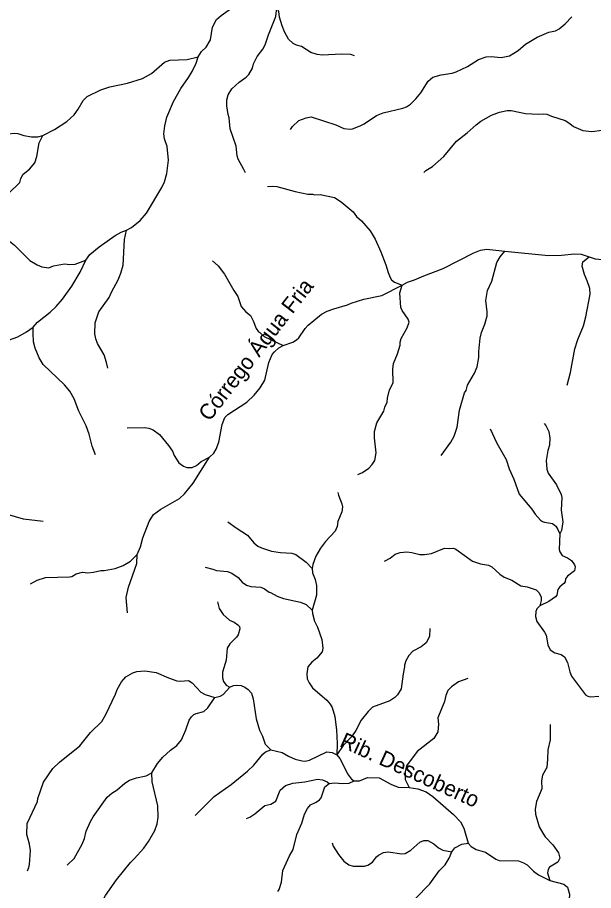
# Model space of a CAD drawing. Extents: x 500 to 555.2, y 9115.7 to 9171.
# Drawn here: x 535.02 to 540.92, y 9143.36 to 9152.3 of the extents above; entities that cross this region are included whole.
import ezdxf
from ezdxf.enums import TextEntityAlignment as Align

# ---------------------------------------------------------------- set-up
doc = ezdxf.new("R2010")
doc.units = 0
doc.header["$LTSCALE"] = 0.064
doc.layers.add('61', color=7, linetype='Continuous')
doc.layers.add('7', color=7, linetype='Continuous', lineweight=25)

msp = doc.modelspace()

# ---------------------------------------------------------------- linework, layer by layer
at = {"layer": '7'}
for points in [[(536.8687, 9151.8985), (536.9035, 9151.9524), (536.9505, 9151.9948), (536.9947, 9152.071), (537.0167, 9152.2028), (537.0572, 9152.2802), (537.1041, 9152.3224), (537.2347, 9152.4119), (537.3382, 9152.5218), (537.4017, 9152.6037), (537.575, 9152.7884), (537.6776, 9152.8682), (537.7376, 9152.9031)], [(537.3545, 9150.7074), (537.3378, 9150.7418), (537.2785, 9150.8504), (537.2688, 9150.8828), (537.2588, 9150.9811), (537.1982, 9151.1583), (537.1883, 9151.2725), (537.1754, 9151.3082), (537.1621, 9151.395), (537.1638, 9151.4579), (537.1762, 9151.5081), (537.2149, 9151.57), (537.289, 9151.638), (537.3621, 9151.6897), (537.3881, 9151.7155), (537.4259, 9151.7827), (537.4377, 9151.8242), (537.4735, 9151.8991), (537.5329, 9151.9761), (537.5572, 9152.0205), (537.5886, 9152.1227), (537.6652, 9152.3116), (537.6764, 9152.398)], [(538.473, 9151.9077), (538.4349, 9151.9208), (538.3371, 9151.9258), (538.1408, 9151.9146), (538.0893, 9151.9213), (538.0255, 9151.9405), (537.9294, 9152.0047), (537.8767, 9152.0181), (537.8419, 9152.0349), (537.7945, 9152.0795), (537.7544, 9152.152), (537.7307, 9152.2134), (537.7033, 9152.3021), (537.696, 9152.3616), (537.6764, 9152.398)], [(537.8149, 9151.1529), (537.8371, 9151.1837), (537.9019, 9151.2434), (537.9752, 9151.2728), (538.0263, 9151.283), (538.2814, 9151.2023), (538.3618, 9151.1643), (538.4278, 9151.1567), (538.45, 9151.1597), (538.5289, 9151.1889), (538.57, 9151.2111), (538.6976, 9151.2977), (538.7664, 9151.3239), (538.9664, 9151.3699), (539.0046, 9151.3841), (539.0475, 9151.4118), (539.1021, 9151.4662), (539.1515, 9151.5276), (539.2285, 9151.6465), (539.2765, 9151.688), (539.3608, 9151.7144), (539.4736, 9151.7305), (539.5155, 9151.7426), (539.6312, 9151.799), (539.7423, 9151.8685), (539.8236, 9151.8957), (539.8718, 9151.8996), (539.9748, 9151.8915), (540.0608, 9151.9088), (540.149, 9151.962), (540.2246, 9152.0259), (540.3464, 9152.0991), (540.4656, 9152.1489), (540.5345, 9152.1654), (540.5707, 9152.1856), (540.6313, 9152.2343), (540.702, 9152.3083)], [(535.2749, 9151.0905), (535.3951, 9151.1524), (535.5223, 9151.2358), (535.5956, 9151.3026), (535.6382, 9151.3617), (535.6892, 9151.4502), (535.7297, 9151.4923), (535.8696, 9151.5584), (535.9633, 9151.5908), (536.1433, 9151.6277), (536.2967, 9151.6768), (536.3887, 9151.7273), (536.5229, 9151.8412), (536.5796, 9151.8636), (536.7559, 9151.8698), (536.8687, 9151.8985)], [(536.1348, 9150.1218), (536.1835, 9150.1502), (536.2752, 9150.2221), (536.339, 9150.296), (536.4977, 9150.558), (536.5228, 9150.6183), (536.5475, 9150.7013), (536.565, 9150.8394), (536.5503, 9150.9772), (536.5243, 9151.0559), (536.5175, 9151.109), (536.5255, 9151.1904), (536.5482, 9151.2782), (536.6173, 9151.4398), (536.69, 9151.5722), (536.7704, 9151.6853), (536.8074, 9151.748), (536.8469, 9151.8335), (536.8687, 9151.8985)], [(539.1821, 9150.7125), (539.2048, 9150.7333), (539.2721, 9150.7737), (539.3896, 9150.8778), (539.5171, 9151.0348), (539.6274, 9151.1173), (539.7181, 9151.2012), (539.7669, 9151.2369), (539.8782, 9151.3005), (539.9605, 9151.3321), (540.0391, 9151.3469), (540.0785, 9151.3485), (540.2249, 9151.3155), (540.3569, 9151.3092), (540.4104, 9151.314), (540.4453, 9151.3092), (540.493, 9151.2882), (540.634, 9151.2438), (540.6788, 9151.2156), (540.7161, 9151.1838), (540.814, 9151.1435), (540.9072, 9151.132), (541.0129, 9151.145)], [(534.2993, 9150.5826), (534.3844, 9150.6336), (534.4519, 9150.6936), (534.5291, 9150.8231), (534.584, 9150.883), (534.6787, 9150.9495), (534.7842, 9151.0372), (534.8723, 9151.0926), (534.9227, 9151.1093), (534.9815, 9151.1156), (535.0204, 9151.1121), (535.0795, 9151.0909), (535.1597, 9151.078), (535.2236, 9151.0792), (535.2749, 9151.0905)], [(534.8546, 9150.3593), (534.924, 9150.4967), (535.0397, 9150.6101), (535.0494, 9150.6497), (535.0753, 9150.6951), (535.1385, 9150.7453), (535.194, 9150.8101), (535.2146, 9150.8748), (535.2393, 9151.016), (535.2749, 9151.0905)], [(537.5802, 9150.5673), (537.6348, 9150.5729), (537.6759, 9150.5702), (537.8628, 9150.5165), (537.9927, 9150.489), (538.044, 9150.489), (538.0616, 9150.4842), (538.1212, 9150.4873), (538.2653, 9150.4574), (538.3365, 9150.4119), (538.4583, 9150.3081), (538.4938, 9150.2631), (538.5432, 9150.2167), (538.6334, 9150.1149), (538.6829, 9150.0292), (538.7433, 9149.8985), (538.7942, 9149.7673), (538.8159, 9149.6872), (538.8372, 9149.6355), (538.852, 9149.6144), (538.8838, 9149.5889), (538.9597, 9149.5569)], [(540.8775, 9149.8475), (540.9406, 9149.8285), (541.0561, 9149.8166), (541.1775, 9149.8411), (541.3016, 9149.9162), (541.4209, 9150.0286), (541.4996, 9150.1427), (541.5347, 9150.258), (541.5497, 9150.3761), (541.5468, 9150.4412)], [(535.7156, 9149.8151), (535.7581, 9149.8738), (535.8521, 9149.9513), (536.0193, 9150.0682)], [(535.9431, 9148.7066), (535.93, 9148.7673), (535.904, 9148.8454), (535.8377, 9148.9614), (535.8191, 9149.0083), (535.8089, 9149.0587), (535.8123, 9149.1728), (535.85, 9149.2864), (535.9568, 9149.4332), (535.9795, 9149.4866), (536.0474, 9149.6128), (536.0747, 9149.6809), (536.0991, 9149.7646), (536.1144, 9150.0256), (536.1348, 9150.1218)], [(536.0193, 9150.0682), (536.0802, 9150.1005), (536.1348, 9150.1218)], [(534.5061, 9149.9934), (534.6011, 9150.035), (534.6918, 9150.0526), (534.8166, 9150.0494), (534.8749, 9150.0364), (534.9346, 9150.0084), (534.987, 9149.969), (535.144, 9149.8111), (535.2181, 9149.7649), (535.2648, 9149.7448), (535.3372, 9149.7362), (535.3853, 9149.7577), (535.4988, 9149.7755), (535.5513, 9149.7706), (535.608, 9149.7746), (535.7156, 9149.8151)], [(538.9597, 9149.5569), (539.0158, 9149.5881), (539.0872, 9149.6112), (539.1846, 9149.6541), (539.3824, 9149.7277), (539.6974, 9149.89), (539.7643, 9149.9151), (539.8292, 9149.9264), (540.0128, 9149.9079)], [(539.3598, 9147.8141), (539.4601, 9147.9499), (539.4931, 9148.0095), (539.5241, 9148.1017), (539.5487, 9148.2773), (539.5996, 9148.4548), (539.6156, 9148.4793), (539.6321, 9148.5333), (539.7032, 9148.6558), (539.7309, 9148.7214), (539.747, 9148.8186), (539.7456, 9148.8795), (539.7601, 9149.0147), (539.7747, 9149.0739), (539.8078, 9149.1585), (539.8308, 9149.2425), (539.8341, 9149.285), (539.8194, 9149.4018), (539.836, 9149.5021), (539.8818, 9149.6006), (539.9307, 9149.7896), (539.965, 9149.8471), (540.0128, 9149.9079)], [(540.0128, 9149.9079), (540.4617, 9149.8625), (540.5962, 9149.864), (540.7275, 9149.8788), (540.7955, 9149.8756), (540.8775, 9149.8475)], [(535.1763, 9149.1273), (535.2206, 9149.1788), (535.351, 9149.2819), (535.4115, 9149.3387), (535.4762, 9149.4152), (535.5746, 9149.548), (535.6602, 9149.6898), (535.7156, 9149.8151)], [(537.0147, 9149.8065), (537.0735, 9149.7574), (537.1391, 9149.672), (537.234, 9149.5021), (537.2745, 9149.4408), (537.3088, 9149.3407), (537.3567, 9149.2839), (537.4045, 9149.2477), (537.4343, 9149.1932), (537.4639, 9149.1145), (537.4865, 9149.0797), (537.5025, 9149.0725), (537.5472, 9149.0334), (537.7413, 9148.9389)], [(540.6527, 9148.5337), (540.687, 9148.6618), (540.7314, 9148.9045), (540.7637, 9149.0017), (540.8199, 9149.1408), (540.8445, 9149.2335), (540.8872, 9149.4649), (540.8839, 9149.5245), (540.859, 9149.6038), (540.8296, 9149.6663), (540.8053, 9149.7528), (540.8131, 9149.7981), (540.8775, 9149.8475)], [(537.7413, 9148.9389), (537.8384, 9148.9754), (537.8761, 9148.9965), (537.8996, 9149.0173), (537.9659, 9149.1144), (537.9966, 9149.1483), (538.1322, 9149.2601), (538.1916, 9149.2912), (538.2596, 9149.3157), (538.4015, 9149.3554), (538.4364, 9149.3724), (538.5688, 9149.4144), (538.7514, 9149.4514), (538.9597, 9149.5569)], [(538.5045, 9147.6192), (538.5535, 9147.6385), (538.6187, 9147.6825), (538.6543, 9147.7214), (538.6796, 9147.7607), (538.6942, 9147.8419), (538.6778, 9147.9926), (538.6761, 9148.0575), (538.7019, 9148.1488), (538.774, 9148.2671), (538.7847, 9148.3084), (538.8072, 9148.3611), (538.8106, 9148.3998), (538.8314, 9148.4864), (538.8678, 9148.5558), (538.8664, 9148.696), (538.8715, 9148.7543), (538.9143, 9148.8535), (538.9399, 9148.9432), (538.9402, 9148.9728), (538.9499, 9149.0116), (539.011, 9149.1216), (539.0316, 9149.1786), (539.0234, 9149.2102), (538.9603, 9149.2976), (538.9482, 9149.3292), (538.9353, 9149.4788), (538.9597, 9149.5569)], [(534.8717, 9148.9677), (534.8724, 9148.9693), (534.925, 9148.9951), (535.0196, 9149.0298), (535.109, 9149.0804), (535.1763, 9149.1273)], [(535.8176, 9147.8206), (535.7831, 9147.9093), (535.7527, 9148.031), (535.7205, 9148.1166), (535.6446, 9148.2659), (535.5972, 9148.3927), (535.5536, 9148.4736), (535.4983, 9148.5374), (535.2777, 9148.7467), (535.2397, 9148.8126), (535.1988, 9148.9111), (535.1803, 9148.9792), (535.1758, 9149.0652), (535.1763, 9149.1273)], [(536.9865, 9147.7952), (537.0282, 9147.8379), (537.0524, 9147.8784), (537.0802, 9147.9505), (537.1163, 9148.131), (537.1413, 9148.2029), (537.1718, 9148.2346), (537.3666, 9148.3578), (537.4438, 9148.4316), (537.5036, 9148.5048), (537.5508, 9148.5864), (537.5919, 9148.7667), (537.6286, 9148.8462), (537.6521, 9148.8762), (537.6975, 9148.9147), (537.7406, 9148.9386), (537.7413, 9148.9389)], [(536.1417, 9148.0964), (536.3218, 9148.0991), (536.3627, 9148.0938), (536.4063, 9148.0756), (536.4715, 9148.027), (536.5657, 9147.9171), (536.6059, 9147.8563), (536.6232, 9147.814), (536.671, 9147.7376), (536.719, 9147.7051), (536.7519, 9147.6909), (536.8079, 9147.6884), (536.8509, 9147.7092), (536.9002, 9147.7517), (536.9865, 9147.7952)], [(540.4177, 9148.1404), (540.4342, 9148.1218), (540.4641, 9148.0576), (540.4738, 9147.9892), (540.4723, 9147.9182), (540.4544, 9147.8651), (540.438, 9147.7622), (540.445, 9147.6717), (540.4571, 9147.6312), (540.5443, 9147.5118), (540.5916, 9147.4124), (540.5985, 9147.3817), (540.5921, 9147.2534), (540.6082, 9147.1324), (540.5956, 9147.043), (540.5766, 9147.009)], [(539.8628, 9148.0856), (539.9303, 9147.9378), (540.0258, 9147.7709), (540.0586, 9147.6749), (540.1064, 9147.5692), (540.1589, 9147.4158), (540.2917, 9147.2642), (540.3263, 9147.2118), (540.3794, 9147.1503), (540.3998, 9147.1368), (540.4198, 9147.1314), (540.5011, 9147.1149), (540.5359, 9147.0905), (540.5578, 9147.0539), (540.5766, 9147.009)], [(536.2429, 9146.7974), (536.2443, 9146.7988), (536.2763, 9146.8762), (536.3015, 9146.9704), (536.3664, 9147.1356), (536.4121, 9147.2078), (536.4864, 9147.2616), (536.6761, 9147.3738), (536.7279, 9147.4189), (536.8176, 9147.5283), (536.9865, 9147.7952)], [(538.3007, 9147.4348), (538.3077, 9147.405), (538.3433, 9147.3195), (538.3496, 9147.2872), (538.3416, 9147.2353), (538.3022, 9147.1362), (538.2934, 9147.0858), (538.2722, 9147.0374), (538.1737, 9146.9307), (538.1236, 9146.8628), (538.0738, 9146.7814), (538.0452, 9146.6974), (538.0384, 9146.656)], [(535.279, 9147.1352), (535.0764, 9147.1614), (534.857, 9147.2263), (534.7607, 9147.2248), (534.6531, 9147.2085), (534.5777, 9147.2149), (534.5371, 9147.2268), (534.4911, 9147.2622)], [(537.172, 9147.135), (537.2573, 9147.0723), (537.3737, 9146.9968), (537.4406, 9146.9185), (537.4797, 9146.8848), (537.5186, 9146.8656), (537.6221, 9146.8334), (537.7139, 9146.82), (537.8307, 9146.8115), (537.8707, 9146.7999), (537.9773, 9146.7212), (538.0384, 9146.656)], [(540.5766, 9147.009), (540.5722, 9146.8497), (540.5789, 9146.8246), (540.6018, 9146.7889), (540.6565, 9146.7652), (540.6964, 9146.7381), (540.7279, 9146.6935), (540.7344, 9146.671), (540.7275, 9146.6308), (540.6561, 9146.5754), (540.6365, 9146.5502), (540.6313, 9146.5185), (540.6202, 9146.5007), (540.5772, 9146.4686), (540.5559, 9146.44), (540.5479, 9146.3834), (540.5348, 9146.3642), (540.4659, 9146.3188), (540.3726, 9146.2742)], [(538.7785, 9146.7288), (538.8392, 9146.7612), (538.8882, 9146.8009), (538.9392, 9146.82), (539.0096, 9146.8246), (539.0589, 9146.8194), (539.1409, 9146.8), (539.1908, 9146.7984), (539.2632, 9146.8098), (539.3957, 9146.8621), (539.4478, 9146.8619), (539.4883, 9146.8648), (539.5114, 9146.8532), (539.6817, 9146.7295), (539.763, 9146.7018), (539.8452, 9146.6887), (539.8817, 9146.6719), (539.9615, 9146.5988), (540.0058, 9146.5675), (540.0857, 9146.5356), (540.1791, 9146.4791), (540.2425, 9146.467), (540.336, 9146.4356), (540.3606, 9146.4096), (540.3866, 9146.3653), (540.3868, 9146.3266), (540.3726, 9146.2742)], [(535.148, 9146.4992), (535.2179, 9146.5364), (535.3041, 9146.5635), (535.5507, 9146.5704), (535.5729, 9146.5725), (535.617, 9146.6013), (535.6825, 9146.6178), (535.7359, 9146.6113), (535.7968, 9146.6164), (535.8716, 9146.6339), (535.9038, 9146.6341), (536.0166, 9146.6555), (536.0992, 9146.6852), (536.1758, 9146.729), (536.2429, 9146.7974)], [(536.1434, 9146.2018), (536.1304, 9146.3566), (536.1547, 9146.4625), (536.2401, 9146.7057), (536.2429, 9146.7974)], [(536.9398, 9146.6684), (537.0176, 9146.6496), (537.0579, 9146.6333), (537.1694, 9146.6261), (537.2157, 9146.6092), (537.2785, 9146.5638), (537.3209, 9146.515), (537.3639, 9146.4843), (537.4076, 9146.4722), (537.5106, 9146.4651), (537.5474, 9146.448), (537.5963, 9146.4117), (537.6115, 9146.4092), (537.6776, 9146.3724), (537.7438, 9146.3476), (537.918, 9146.3107), (537.9757, 9146.2864), (538.0386, 9146.2281)], [(538.0384, 9146.656), (538.0426, 9146.6097), (538.0677, 9146.5419), (538.0833, 9146.4796), (538.0823, 9146.3817), (538.0386, 9146.2281)], [(537.0673, 9146.3154), (537.0834, 9146.244), (537.1235, 9146.1827), (537.1895, 9146.1247), (537.2378, 9146.1059), (537.2769, 9146.0783), (537.2917, 9146.0596), (537.2965, 9146.0373), (537.2798, 9145.9751), (537.2619, 9145.9504), (537.1937, 9145.8835), (537.1669, 9145.8398), (537.1554, 9145.7159), (537.1198, 9145.5924), (537.1192, 9145.5342), (537.1288, 9145.4971), (537.1547, 9145.4608), (537.1932, 9145.4392)], [(538.0386, 9146.2281), (538.041, 9146.1927), (538.0617, 9146.1171), (538.0921, 9146.0536), (538.1363, 9145.929), (538.1462, 9145.8398), (538.1391, 9145.801), (538.0855, 9145.7355), (538.036, 9145.6973), (537.9949, 9145.6477), (537.984, 9145.5754), (537.9868, 9145.5256), (538.0059, 9145.4854), (538.0422, 9145.4331), (538.1869, 9145.3078), (538.2229, 9145.2646), (538.2413, 9145.2302), (538.2708, 9145.1384), (538.2873, 9145), (538.2956, 9144.8628), (538.292, 9144.7454)], [(540.3726, 9146.2742), (540.3408, 9146.2414), (540.3319, 9146.2137), (540.3279, 9146.1648), (540.3428, 9146.1128), (540.42, 9146.0038), (540.4361, 9145.9716), (540.4557, 9145.8739), (540.477, 9145.8231), (540.5273, 9145.79), (540.5929, 9145.7749), (540.6246, 9145.7502), (540.6558, 9145.6928), (540.6785, 9145.5959), (540.6971, 9145.5517), (540.8418, 9145.3626), (540.8633, 9145.3483), (540.8928, 9145.3417), (540.9763, 9145.3465)], [(539.2454, 9146.0397), (539.2401, 9145.958), (539.2078, 9145.8935), (539.1552, 9145.8531), (539.0694, 9145.8072), (539.03, 9145.7644), (538.9969, 9145.708), (538.9846, 9145.6642), (538.9859, 9145.6476), (538.9701, 9145.5747), (538.9501, 9145.4211), (538.9126, 9145.3604), (538.8846, 9145.3345), (538.834, 9145.3011), (538.6577, 9145.2341), (538.6113, 9145.1918), (538.5403, 9145.1011), (538.4844, 9144.9946), (538.4415, 9144.9318), (538.3568, 9144.8433), (538.292, 9144.7454)], [(535.1183, 9143.5582), (535.1331, 9143.5921), (535.1396, 9143.6234), (535.1479, 9143.7657), (535.1395, 9143.83), (535.1132, 9143.9292), (535.1154, 9144.0441), (535.2196, 9144.2685), (535.2234, 9144.2979), (535.2825, 9144.4659), (535.3784, 9144.6079), (535.4454, 9144.6701), (535.656, 9144.8394), (535.7646, 9144.9743), (535.8793, 9145.0892), (535.9223, 9145.1587), (536.0204, 9145.3681), (536.0372, 9145.4144), (536.0812, 9145.4927), (536.1278, 9145.5458), (536.1997, 9145.5872), (536.2408, 9145.6009), (536.3223, 9145.6075), (536.4371, 9145.5911), (536.5651, 9145.535), (536.6517, 9145.5046), (536.6878, 9145.501), (536.7693, 9145.507), (536.8071, 9145.4852), (536.8964, 9145.3894), (536.9396, 9145.3662), (537.0403, 9145.3333)], [(539.6332, 9145.5272), (539.5401, 9145.494), (539.4658, 9145.4443), (539.4303, 9145.4069), (539.4077, 9145.3549), (539.394, 9145.2914), (539.3275, 9145.1259), (539.3322, 9145.0596), (539.3256, 9144.9815), (539.2842, 9144.9133), (539.1138, 9144.7818), (539.0067, 9144.6323), (538.9903, 9144.5722), (538.9903, 9144.4938), (539.0311, 9144.4105)], [(537.0403, 9145.3333), (537.0931, 9145.3483), (537.1253, 9145.3645), (537.1932, 9145.4392)], [(537.1932, 9145.4392), (537.2321, 9145.4553), (537.2658, 9145.4612), (537.3097, 9145.458), (537.3468, 9145.4381), (537.3806, 9145.4165), (537.4143, 9145.3794), (537.4329, 9145.3206), (537.4637, 9145.1161), (537.4991, 9144.9998), (537.5301, 9144.9377), (537.5557, 9144.8568), (537.615, 9144.7969)], [(536.3929, 9144.563), (536.4513, 9144.6591), (536.5055, 9144.7229), (536.5848, 9144.7939), (536.6508, 9144.8436), (536.6974, 9144.8984), (536.7433, 9145.0025), (536.778, 9145.1017), (536.8, 9145.137), (536.8231, 9145.1583), (536.8466, 9145.1708), (536.926, 9145.1906), (536.9693, 9145.2266), (537.0403, 9145.3333)], [(540.4788, 9145.0557), (540.4771, 9144.8995), (540.4539, 9144.7985), (540.4525, 9144.7016), (540.443, 9144.6157), (540.4, 9144.5375), (540.3902, 9144.4803), (540.3918, 9144.3991), (540.3376, 9144.2691), (540.3246, 9144.1883), (540.3291, 9144.1398), (540.3673, 9144.01), (540.4029, 9143.9433), (540.4283, 9143.9077), (540.5049, 9143.8245), (540.564, 9143.7425), (540.5767, 9143.6891), (540.5587, 9143.6476), (540.4703, 9143.5956), (540.4594, 9143.5725), (540.4526, 9143.5375), (540.4757, 9143.4591)], [(536.837, 9144.1251), (537.0342, 9144.3182), (537.2085, 9144.4433), (537.3738, 9144.5801), (537.4385, 9144.6406), (537.5317, 9144.7537), (537.5598, 9144.7755), (537.615, 9144.7969)], [(537.615, 9144.7969), (537.6155, 9144.7964), (537.7302, 9144.7705), (537.7958, 9144.7312), (537.8635, 9144.7008), (537.9357, 9144.6843), (537.9648, 9144.6827), (538.0092, 9144.6926), (538.1873, 9144.7774), (538.244, 9144.771), (538.292, 9144.7454)], [(538.292, 9144.7454), (538.3212, 9144.7104), (538.3448, 9144.6661), (538.3986, 9144.5501), (538.4428, 9144.4964), (538.4674, 9144.4802)], [(535.5262, 9143.6153), (535.5979, 9143.6842), (535.6808, 9143.8295), (535.7044, 9143.8906), (535.7215, 9143.966), (535.7639, 9144.0644), (535.7907, 9144.112), (535.9356, 9144.3138), (535.9834, 9144.3553), (536.0379, 9144.3885), (536.1158, 9144.4559), (536.1643, 9144.4869), (536.237, 9144.5117), (536.3355, 9144.5303), (536.3929, 9144.563)], [(535.8279, 9143.0382), (535.8385, 9143.0985), (535.8846, 9143.2428), (535.9174, 9143.3044), (536.0326, 9143.4657), (536.1747, 9143.6424), (536.2135, 9143.6797), (536.3104, 9143.7912), (536.3603, 9143.858), (536.4244, 9143.9718), (536.4469, 9144.0394), (536.4599, 9144.1084), (536.4567, 9144.2225), (536.3979, 9144.4686), (536.3929, 9144.563)], [(538.4674, 9144.4802), (538.5224, 9144.4801), (538.6062, 9144.5134), (538.7236, 9144.51), (538.8446, 9144.4449), (538.9199, 9144.4153), (539.0311, 9144.4105)], [(537.364, 9144.0956), (537.3993, 9144.1089), (537.4501, 9144.1432), (537.5539, 9144.2276), (537.6144, 9144.2406), (537.6651, 9144.2701), (537.7081, 9144.3833), (537.763, 9144.4333), (537.8412, 9144.456), (537.9626, 9144.4696), (538.0933, 9144.4986), (538.1434, 9144.4893), (538.1932, 9144.4693), (538.2111, 9144.4537)], [(537.6865, 9143.3469), (537.6996, 9143.3674), (537.7245, 9143.4417), (537.7381, 9143.561), (537.8053, 9143.7119), (537.8413, 9143.7776), (537.8809, 9143.9317), (537.9325, 9144.0478), (537.9598, 9144.1392), (537.9889, 9144.1969), (538.0218, 9144.2328), (538.079, 9144.2609), (538.1115, 9144.2839), (538.1287, 9144.3064), (538.1662, 9144.4182), (538.2111, 9144.4537)], [(538.2111, 9144.4537), (538.2664, 9144.4611), (538.3478, 9144.4538), (538.4158, 9144.4561), (538.4674, 9144.4802)], [(539.0311, 9144.4105), (539.1208, 9144.3988), (539.2053, 9144.3676), (539.2767, 9144.3192), (539.4875, 9144.135), (539.5573, 9144.0588), (539.5931, 9143.9959), (539.6366, 9143.8404)], [(538.2435, 9143.844), (538.2548, 9143.8113), (538.3067, 9143.7251), (538.3628, 9143.6557), (538.4139, 9143.6185), (538.46, 9143.6048), (538.576, 9143.6064), (538.6083, 9143.6176), (538.6551, 9143.6461), (538.6966, 9143.7005), (538.7181, 9143.7187), (538.7698, 9143.7446), (538.8168, 9143.7538), (538.9566, 9143.7311), (538.99, 9143.7362), (539.0484, 9143.7688), (539.143, 9143.8531), (539.1818, 9143.8704), (539.2233, 9143.8671), (539.284, 9143.8361), (539.3323, 9143.7951), (539.3777, 9143.768), (539.4717, 9143.7537)], [(539.4717, 9143.7537), (539.5018, 9143.7934), (539.5728, 9143.8324), (539.6366, 9143.8404)], [(539.6366, 9143.8404), (539.6367, 9143.8399), (539.6679, 9143.8064), (539.7183, 9143.7759), (539.8155, 9143.7476), (539.9229, 9143.6778), (539.9565, 9143.6625), (540.1533, 9143.6605), (540.2065, 9143.6408), (540.243, 9143.6207), (540.3082, 9143.5556), (540.3605, 9143.5169), (540.4757, 9143.4591)], [(538.4211, 9142.9089), (538.463, 9142.9004), (538.6288, 9142.837), (538.7204, 9142.8519), (538.7958, 9142.8962), (538.847, 9142.9375), (538.8656, 9142.9634), (538.8875, 9143.0207), (538.8934, 9143.0906), (538.9229, 9143.1446), (538.953, 9143.1713), (539.0373, 9143.2262), (539.0934, 9143.2708), (539.2457, 9143.4264), (539.3395, 9143.5593), (539.4027, 9143.6195), (539.444, 9143.6873), (539.4717, 9143.7537)], [(540.4757, 9143.4591), (540.6203, 9143.4221), (540.6561, 9143.3891), (540.6752, 9143.3193), (540.6661, 9143.1597), (540.681, 9143.1286), (540.7356, 9143.0675), (540.7516, 9143.0422)]]:
    msp.add_lwpolyline(points, dxfattribs=at)

# ---------------------------------------------------------------- texts
at = {"layer": '61'}
for s, rotation, p in [('Córrego Água Fria', 52.306, (537.523, 9148.8502)), ('Rib. Descoberto', 335.556, (539.0076, 9144.5189))]:
    msp.add_text(s, height=0.16, rotation=rotation, dxfattribs=at).set_placement(p, align=Align.CENTER)

doc.saveas('drawing.dxf')
